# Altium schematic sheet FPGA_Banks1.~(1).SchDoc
size A4
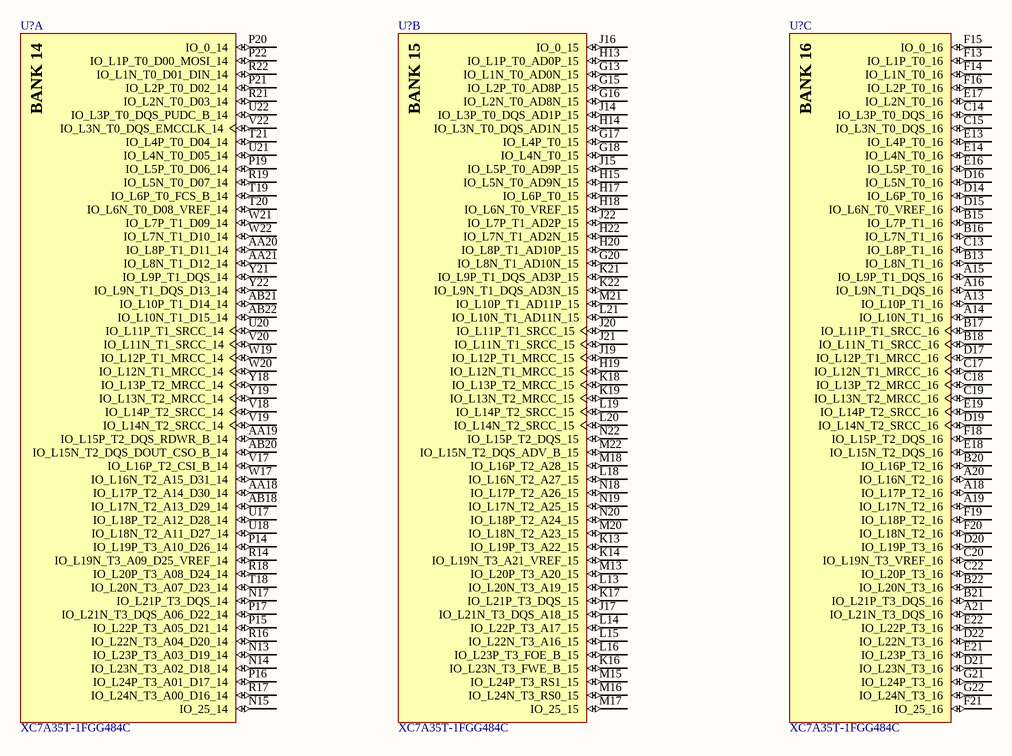
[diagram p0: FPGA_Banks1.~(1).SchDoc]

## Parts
(Parts that share a designator on the sheet are numbered #1, #2 ... from top to bottom, then left to right.)
U?#1  XC7A35T-1FGG484C  [FGG484]  (part A of 12)
U?#2  XC7A35T-1FGG484C  [FGG484]  (part B of 12)
U?#3  XC7A35T-1FGG484C  [FGG484]  (part C of 12)

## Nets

Not connected (* = marked no-connect by the designer): U?#1 AA18(IO_L17P_T2_A14_D30_14) AA19(IO_L15P_T2_DQS_RDWR_B_14) AA20(IO_L8P_T1_D11_14) AA21(IO_L8N_T1_D12_14) AB18(IO_L17N_T2_A13_D29_14) AB20(IO_L15N_T2_DQS_DOUT_CSO_B_14) AB21(IO_L10P_T1_D14_14) AB22(IO_L10N_T1_D15_14) N13(IO_L23P_T3_A03_D19_14) N14(IO_L23N_T3_A02_D18_14) N15(IO_25_14) N17(IO_L21P_T3_DQS_14) P14(IO_L19P_T3_A10_D26_14) P15(IO_L22P_T3_A05_D21_14) P16(IO_L24P_T3_A01_D17_14) P17(IO_L21N_T3_DQS_A06_D22_14) P19(IO_L5P_T0_D06_14) P20(IO_0_14) P21(IO_L2P_T0_D02_14) P22(IO_L1P_T0_D00_MOSI_14) R14(IO_L19N_T3_A09_D25_VREF_14) R16(IO_L22N_T3_A04_D20_14) R17(IO_L24N_T3_A00_D16_14) R18(IO_L20P_T3_A08_D24_14) R19(IO_L5N_T0_D07_14) R21(IO_L2N_T0_D03_14) R22(IO_L1N_T0_D01_DIN_14) T18(IO_L20N_T3_A07_D23_14) T19(IO_L6P_T0_FCS_B_14) T20(IO_L6N_T0_D08_VREF_14) T21(IO_L4P_T0_D04_14) U17(IO_L18P_T2_A12_D28_14) U18(IO_L18N_T2_A11_D27_14) U20(IO_L11P_T1_SRCC_14) U21(IO_L4N_T0_D05_14) U22(IO_L3P_T0_DQS_PUDC_B_14) V17(IO_L16P_T2_CSI_B_14) V18(IO_L14P_T2_SRCC_14) V19(IO_L14N_T2_SRCC_14) V20(IO_L11N_T1_SRCC_14) V22(IO_L3N_T0_DQS_EMCCLK_14) W17(IO_L16N_T2_A15_D31_14) W19(IO_L12P_T1_MRCC_14) W20(IO_L12N_T1_MRCC_14) W21(IO_L7P_T1_D09_14) W22(IO_L7N_T1_D10_14) Y18(IO_L13P_T2_MRCC_14) Y19(IO_L13N_T2_MRCC_14) Y21(IO_L9P_T1_DQS_14) Y22(IO_L9N_T1_DQS_D13_14); U?#2 G13(IO_L1N_T0_AD0N_15) G15(IO_L2P_T0_AD8P_15) G16(IO_L2N_T0_AD8N_15) G17(IO_L4P_T0_15) G18(IO_L4N_T0_15) G20(IO_L8N_T1_AD10N_15) H13(IO_L1P_T0_AD0P_15) H14(IO_L3N_T0_DQS_AD1N_15) H15(IO_L5N_T0_AD9N_15) H17(IO_L6P_T0_15) H18(IO_L6N_T0_VREF_15) H19(IO_L12N_T1_MRCC_15) H20(IO_L8P_T1_AD10P_15) H22(IO_L7N_T1_AD2N_15) J14(IO_L3P_T0_DQS_AD1P_15) J15(IO_L5P_T0_AD9P_15) J16(IO_0_15) J17(IO_L21N_T3_DQS_A18_15) J19(IO_L12P_T1_MRCC_15) J20(IO_L11P_T1_SRCC_15) J21(IO_L11N_T1_SRCC_15) J22(IO_L7P_T1_AD2P_15) K13(IO_L19P_T3_A22_15) K14(IO_L19N_T3_A21_VREF_15) K16(IO_L23N_T3_FWE_B_15) K17(IO_L21P_T3_DQS_15) K18(IO_L13P_T2_MRCC_15) K19(IO_L13N_T2_MRCC_15) K21(IO_L9P_T1_DQS_AD3P_15) K22(IO_L9N_T1_DQS_AD3N_15) L13(IO_L20N_T3_A19_15) L14(IO_L22P_T3_A17_15) L15(IO_L22N_T3_A16_15) L16(IO_L23P_T3_FOE_B_15) L18(IO_L16N_T2_A27_15) L19(IO_L14P_T2_SRCC_15) L20(IO_L14N_T2_SRCC_15) L21(IO_L10N_T1_AD11N_15) M13(IO_L20P_T3_A20_15) M15(IO_L24P_T3_RS1_15) M16(IO_L24N_T3_RS0_15) M17(IO_25_15) M18(IO_L16P_T2_A28_15) M20(IO_L18N_T2_A23_15) M21(IO_L10P_T1_AD11P_15) M22(IO_L15N_T2_DQS_ADV_B_15) N18(IO_L17P_T2_A26_15) N19(IO_L17N_T2_A25_15) N20(IO_L18P_T2_A24_15) N22(IO_L15P_T2_DQS_15); U?#3 A13(IO_L10P_T1_16) A14(IO_L10N_T1_16) A15(IO_L9P_T1_DQS_16) A16(IO_L9N_T1_DQS_16) A18(IO_L17P_T2_16) A19(IO_L17N_T2_16) A20(IO_L16N_T2_16) A21(IO_L21N_T3_DQS_16) B13(IO_L8N_T1_16) B15(IO_L7P_T1_16) B16(IO_L7N_T1_16) B17(IO_L11P_T1_SRCC_16) B18(IO_L11N_T1_SRCC_16) B20(IO_L16P_T2_16) B21(IO_L21P_T3_DQS_16) B22(IO_L20N_T3_16) C13(IO_L8P_T1_16) C14(IO_L3P_T0_DQS_16) C15(IO_L3N_T0_DQS_16) C17(IO_L12N_T1_MRCC_16) C18(IO_L13P_T2_MRCC_16) C19(IO_L13N_T2_MRCC_16) C20(IO_L19N_T3_VREF_16) C22(IO_L20P_T3_16) D14(IO_L6P_T0_16) D15(IO_L6N_T0_VREF_16) D16(IO_L5N_T0_16) D17(IO_L12P_T1_MRCC_16) D19(IO_L14N_T2_SRCC_16) D20(IO_L19P_T3_16) D21(IO_L23N_T3_16) D22(IO_L22N_T3_16) E13(IO_L4P_T0_16) E14(IO_L4N_T0_16) E16(IO_L5P_T0_16) E17(IO_L2N_T0_16) E18(IO_L15N_T2_DQS_16) E19(IO_L14P_T2_SRCC_16) E21(IO_L23P_T3_16) E22(IO_L22P_T3_16) F13(IO_L1P_T0_16) F14(IO_L1N_T0_16) F15(IO_0_16) F16(IO_L2P_T0_16) F18(IO_L15P_T2_DQS_16) F19(IO_L18P_T2_16) F20(IO_L18N_T2_16) F21(IO_25_16) G21(IO_L24P_T3_16) G22(IO_L24N_T3_16)

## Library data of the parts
U?#1-U?#3 = XC7A35T-1FGG484C: Artix-7 FPGA, 250 User I/Os, 4 GTP, 484-Ball BGA, Speed Grade 1, Commercial Grade, Pb-Free; Manufacturer: Xilinx; Total Block RAM: 1800 Kb; GTP: 4; Clock Mgmt Tiles (CMTs): 5; Logic Cells: 33280; Available User I/O: 250; Speed Grades: 1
